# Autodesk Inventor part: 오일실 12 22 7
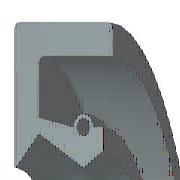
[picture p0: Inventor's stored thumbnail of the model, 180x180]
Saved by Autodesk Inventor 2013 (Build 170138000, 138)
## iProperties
Created: 2012-02
Part Number: 오일실 12 22 7
Material: 고무
Description: 오일-실
Document SubType Name: Modeling
Standard: KS B 2804
Designer: mduedu
Standards Organization: KS
Language: ko-KR
Size Designation: D - 12 22 7
Categories: <MemberInstance><Categories><Category DisplayName="샤프트 부품" InternalName="7f7aeb1f-a693-4053-b835-cee3144e0d98" Mnemonic="SHFT"><Category DisplayName="실링" Intern
Density: 0.93 g/cm^3
Mass: 1.25383 g
Surface Area: 18.4996 cm^2
Volume: 1.3482 cm^3
IsCustomPart: 1
Author: mduedu
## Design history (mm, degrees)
revolve "본체" stored, may be unused: angle "d17" = 90 deg
revolve "스프링1" stored, may be unused: angle "d18" = 90 deg
body "Solid1"
sketch "스케치1"
  geometry: L1 (0, 11)-(7, 11); L2 (7, 9.25)-(1.75, 9.25); L3 (1.75, 7.75)-(4.9, 6); L4 (4.9, 6)-(0, 6); L5 (0, 0)-(9.586, 0) reference; L6 (4.9, 6)-(6.3, 6.875); L7 (0, 18)-(0, -3) reference; L8 (-1.941, 0)-(11.507, 0) reference; L9 (4.2, 8.1)-(1.75, 8.59); L10 (1.75, 8.59)-(1.75, 9.25); L11 (0, 11)-(0, 6.088); L12 (4.9, 6)-(0, 6); L13 (1.75, 7.75)-(0.152, 6.028); L14 (7, 11)-(7, 9.25); L15 (5.6, 8.1)-(6.3, 8.1); L16 (6.3, 8.1)-(6.3, 6.875); C1 r 0.455 at (4.9, 8.1); A1 r 0.7 centre (4.9, 8.1) between (5.6, 8.1) and (4.2, 8.1); A2 r 0.088 centre (0.088, 6.088) between (0, 6.088) and (0.152, 6.028); 1 further point
  constraints: 28 end point, 5 horizontal alignment, 5 point on line, 4 point on circle, 4 vertical alignment, 3 centre point, 3 tangent, 2 collinear, 2 horizontal, 2 perpendicular, 1 coincident, 1 parallel
  dimensions: "d0" = 22 diameter of L1 L5 (= SD2); "d1" = 1.75 distance of L1.end L2.start (= SD); "d2" = 0.91 diameter of C1 (= SPDI); "d3" = 1.4 diameter of A1 (= SPDA); "d4" = 12 diameter of L3.end L5 (= NND); "d5" = 15.5 diameter of L3.start L5 (= TKDM); "d7" = 17.18 diameter of L9.end L5 (= TKDM + 0.24 x SWDT); "d8" = 1.75 distance between parallel lines of L11 L10 (= SD); "d9" = 4.9 distance from line of L11 C1.centre (= SPDST); "d10" = 16.2 diameter of C1.centre L5 (= HLDM); "d11" = 0.0875 radius of A2 (= 0.25 x LAB); "d12" = 6.3 distance between parallel lines of L11 L16 (= SDI); "d13" = 13.75 diameter of L6.end L5 (= ABDM); "d14" = 7 distance from line of L11 L1.end (= SWDT)
fillet "모깎기1" dims "d6" = 0.3 (= RR)
other parameters: "SD2" = 22 [user parameter; used in 1 equation term], "SWDT" = 7 [user parameter; used in 2 equation terms], "RR" = 0.3 [user parameter; used in 1 equation term], "SD" = 1.75 [user parameter; used in 2 equation terms], "NND" = 12 [user parameter; used in 1 equation term], "SPDA" = 1.4 [user parameter; used in 1 equation term], "SPDI" = 0.91 [user parameter; used in 1 equation term], "TKDM" = 15.5 [user parameter; used in 2 equation terms], "HLDM" = 16.2 [user parameter; used in 1 equation term], "ABDM" = 13.75 [user parameter; used in 1 equation term], "SDI" = 6.3 [user parameter; used in 1 equation term], "SPDST" = 4.9 [user parameter; used in 1 equation term], "LAB" = 0.35 [user parameter; used in 1 equation term], "d15" = 0, "d16" = 0, "d19" = 0
